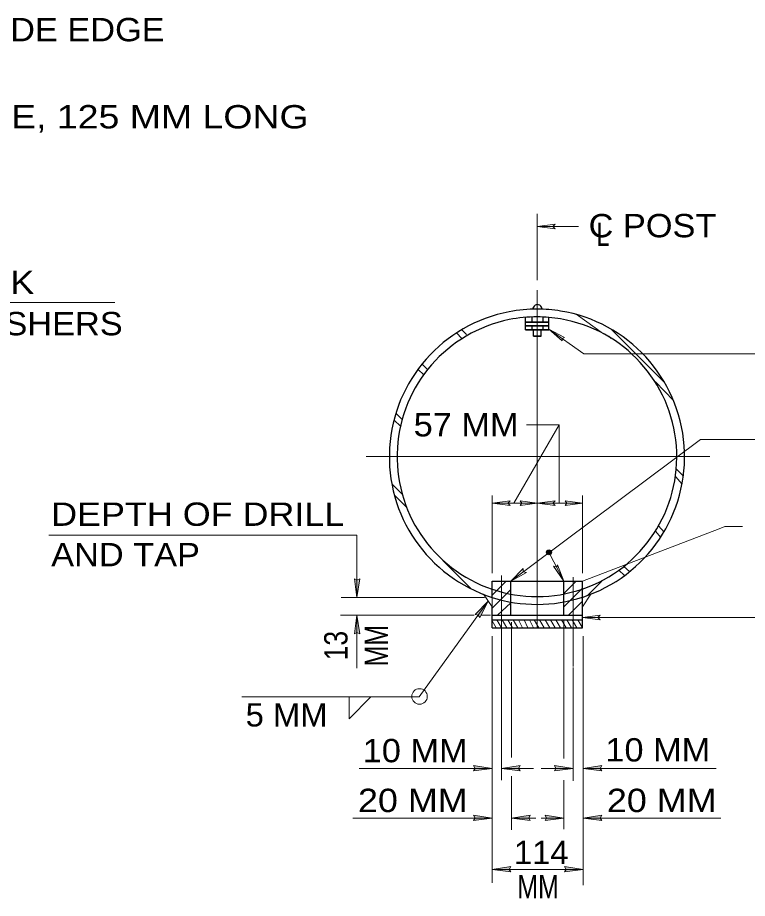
# Model space of a CAD drawing. Extents: x 312601.858 to 312602.699, y 144420.109 to 144420.704.
# Drawn here: x 312602.3399 to 312602.4337, y 144420.327 to 144420.4402 of the extents above; entities that cross this region are included whole.
import ezdxf
from ezdxf.enums import TextEntityAlignment as Align

# ---------------------------------------------------------------- set-up
doc = ezdxf.new("R2010")
doc.units = 0
doc.header["$LTSCALE"] = 0.0012
for name, pattern in [('DOT_DASHED', [7.7, 5, -1.2, 0.3, -1.2]), ('LONG_DASH_SHORT_DASH', [9.9, 6, -1.2, 1.5, -1.2]), ('LONG_DASHED', [7.5, 6, -1.5])]:
    doc.linetypes.add(name, pattern=pattern)
for name, color, linetype, lineweight in [('1', 7, 'Continuous', 25), ('2', 7, 'Continuous', 25), ('39', 7, 'Continuous', 13)]:
    doc.layers.add(name, color=color, linetype=linetype, lineweight=lineweight)

msp = doc.modelspace()

# ---------------------------------------------------------------- hatches: boundary and pattern name
at = {"layer": '1'}
msp.add_hatch(color=256, dxfattribs=at).paths.add_polyline_path([(312602.408516, 144420.3715, 1), (312602.407884, 144420.3715, 1)])
at = {"layer": '39'}
for points in [[(312602.3835, 144420.3679), (312602.3839, 144420.3681), (312602.3835, 144420.3657), (312602.3832, 144420.3681)], [(312602.3991, 144420.3634), (312602.3987, 144420.3635), (312602.4004, 144420.3652), (312602.3993, 144420.3631)], [(312602.3835, 144420.3612), (312602.3832, 144420.361), (312602.3835, 144420.3634), (312602.3839, 144420.361)], [(312602.3987, 144420.3437), (312602.3985, 144420.3441), (312602.4009, 144420.3437), (312602.3985, 144420.3434)], [(312602.4043, 144420.3437), (312602.4045, 144420.3434), (312602.4021, 144420.3437), (312602.4045, 144420.3441)], [(312602.4091, 144420.3437), (312602.4089, 144420.3441), (312602.4113, 144420.3437), (312602.4089, 144420.3434)], [(312602.4148, 144420.3437), (312602.415, 144420.3434), (312602.4126, 144420.3437), (312602.415, 144420.3441)], [(312602.3987, 144420.3373), (312602.3985, 144420.3377), (312602.4009, 144420.3373), (312602.3985, 144420.337)], [(312602.4056, 144420.3373), (312602.4058, 144420.337), (312602.4034, 144420.3373), (312602.4058, 144420.3377)], [(312602.4079, 144420.3373), (312602.4077, 144420.3377), (312602.4101, 144420.3373), (312602.4077, 144420.337)], [(312602.4148, 144420.3373), (312602.415, 144420.337), (312602.4126, 144420.3373), (312602.415, 144420.3377)], [(312602.4031, 144420.3307), (312602.4033, 144420.3304), (312602.4009, 144420.3307), (312602.4033, 144420.3311)], [(312602.4104, 144420.3307), (312602.4102, 144420.3311), (312602.4126, 144420.3307), (312602.4102, 144420.3304)]]:
    msp.add_hatch(color=256, dxfattribs=at).paths.add_polyline_path(points)

# ---------------------------------------------------------------- linework, layer by layer
at = {"layer": '1', "lineweight": 13}
for p, q in [((312602.4067, 144420.4065), (312602.4067, 144420.415)), ((312602.4067, 144420.4134), (312602.412, 144420.4134)), ((312602.2746, 144420.4036), (312602.3524, 144420.4036)), ((312602.4117, 144420.4021), (312602.4152, 144420.3996)), ((312602.3976, 144420.3995), (312602.397, 144420.4001)), ((312602.4082, 144420.4002), (312602.4127, 144420.397)), ((312602.4231, 144420.3933), (312602.4162, 144420.4002)), ((312602.397, 144420.399), (312602.3963, 144420.3997)), ((312602.4162, 144420.399), (312602.4159, 144420.3993)), ((312602.4127, 144420.397), (312602.4675, 144420.397)), ((312602.3926, 144420.395), (312602.3919, 144420.3957)), ((312602.3921, 144420.3943), (312602.3914, 144420.395)), ((312602.4242, 144420.391), (312602.4219, 144420.3934)), ((312602.3893, 144420.3886), (312602.3885, 144420.3894)), ((312602.3891, 144420.3877), (312602.3883, 144420.3885)), ((312602.4033, 144420.3678), (312602.4277, 144420.386)), ((312602.4277, 144420.386), (312602.4347, 144420.386)), ((312602.4255, 144420.3813), (312602.4246, 144420.3822)), ((312602.4253, 144420.3803), (312602.4245, 144420.3812)), ((312602.3893, 144420.379), (312602.388, 144420.3803)), ((312602.3899, 144420.3773), (312602.3883, 144420.3789)), ((312602.4009, 144420.3788), (312602.4009, 144420.3688)), ((312602.4125, 144420.3788), (312602.4125, 144420.3688)), ((312602.4125, 144420.3678), (312602.4301, 144420.3745)), ((312602.4226, 144420.3734), (312602.4219, 144420.3742)), ((312602.423, 144420.3741), (312602.4223, 144420.3749)), ((312602.4301, 144420.3745), (312602.4308, 144420.3748)), ((312602.4308, 144420.3748), (312602.4331, 144420.3748)), ((312602.3835, 144420.3737), (312602.3439, 144420.3737)), ((312602.4101, 144420.3678), (312602.4082, 144420.3715)), ((312602.3982, 144420.3668), (312602.3946, 144420.3704)), ((312602.4186, 144420.369), (312602.4178, 144420.3697)), ((312602.4179, 144420.3685), (312602.4172, 144420.3692)), ((312602.396, 144420.3681), (312602.3961, 144420.368)), ((312602.4009, 144420.3677), (312602.4009, 144420.3678)), ((312602.4009, 144420.366), (312602.4027, 144420.3678)), ((312602.4101, 144420.3662), (312602.4117, 144420.3678)), ((312602.4132, 144420.366), (312602.415, 144420.3678)), ((312602.4009, 144420.3643), (312602.4033, 144420.3667)), ((312602.4101, 144420.3645), (312602.4125, 144420.3669)), ((312602.3815, 144420.3657), (312602.3999, 144420.3657)), ((312602.4016, 144420.3634), (312602.4033, 144420.365)), ((312602.4107, 144420.3634), (312602.4125, 144420.3652)), ((312602.3814, 144420.3634), (312602.3986, 144420.3634)), ((312602.3995, 144420.3634), (312602.4007, 144420.3634)), ((312602.4014, 144420.3618), (312602.4009, 144420.3627)), ((312602.4021, 144420.3618), (312602.4015, 144420.3628)), ((312602.4028, 144420.3618), (312602.4022, 144420.3628)), ((312602.4035, 144420.3618), (312602.4029, 144420.3628)), ((312602.4034, 144420.3451), (312602.4034, 144420.3625)), ((312602.4042, 144420.3618), (312602.4036, 144420.3628)), ((312602.4048, 144420.3618), (312602.4043, 144420.3628)), ((312602.4055, 144420.3618), (312602.405, 144420.3628)), ((312602.4062, 144420.3618), (312602.4057, 144420.3628)), ((312602.4069, 144420.3618), (312602.4063, 144420.3628)), ((312602.4076, 144420.3618), (312602.407, 144420.3628)), ((312602.4083, 144420.3618), (312602.4077, 144420.3628)), ((312602.409, 144420.3618), (312602.4084, 144420.3628)), ((312602.4097, 144420.3618), (312602.4091, 144420.3628)), ((312602.4104, 144420.3618), (312602.4098, 144420.3628)), ((312602.4101, 144420.345), (312602.4101, 144420.3628)), ((312602.4111, 144420.3618), (312602.4105, 144420.3628)), ((312602.4118, 144420.3618), (312602.4112, 144420.3628)), ((312602.4125, 144420.3618), (312602.4119, 144420.3628)), ((312602.4124, 144420.3634), (312602.4125, 144420.3635)), ((312602.4125, 144420.3631), (312602.4301, 144420.3631)), ((312602.4301, 144420.3631), (312602.4308, 144420.3631)), ((312602.4308, 144420.3631), (312602.4938, 144420.3631)), ((312602.4009, 144420.329), (312602.4009, 144420.3607)), ((312602.4126, 144420.3287), (312602.4126, 144420.3607)), ((312602.4021, 144420.3437), (312602.4021, 144420.357)), ((312602.4113, 144420.3421), (312602.4113, 144420.3567)), ((312602.3838, 144420.3437), (312602.4009, 144420.3437)), ((312602.4072, 144420.3437), (312602.4113, 144420.3437)), ((312602.4126, 144420.3437), (312602.4297, 144420.3437)), ((312602.4034, 144420.3358), (312602.4034, 144420.3427)), ((312602.4101, 144420.3359), (312602.4101, 144420.3422)), ((312602.383, 144420.3373), (312602.4009, 144420.3373)), ((312602.4034, 144420.3373), (312602.4065, 144420.3373)), ((312602.4072, 144420.3373), (312602.4101, 144420.3373)), ((312602.4126, 144420.3373), (312602.4303, 144420.3373)), ((312602.4009, 144420.3307), (312602.4126, 144420.3307))]:
    msp.add_line(p, q, dxfattribs=at)
at = {"layer": '1', "linetype": 'LONG_DASH_SHORT_DASH', "lineweight": 13}
for p, q in [((312602.4067, 144420.4072), (312602.4067, 144420.4077)), ((312602.3859, 144420.3838), (312602.3847, 144420.3838))]:
    msp.add_line(p, q, dxfattribs=at)
at = {"layer": '1', "linetype": 'DOT_DASHED', "lineweight": 13}
for p, q in [((312602.4067, 144420.3618), (312602.4067, 144420.4052)), ((312602.3847, 144420.3838), (312602.4289, 144420.3838))]:
    msp.add_line(p, q, dxfattribs=at)
at = {"layer": '1'}
for p, q in [((312602.4052, 144420.4001), (312602.4052, 144420.4017)), ((312602.4052, 144420.4011), (312602.4082, 144420.4011)), ((312602.4082, 144420.4011), (312602.4052, 144420.4011)), ((312602.406, 144420.4017), (312602.406, 144420.4011)), ((312602.4074, 144420.4017), (312602.4074, 144420.4011)), ((312602.4082, 144420.4001), (312602.4082, 144420.4017)), ((312602.4052, 144420.4006), (312602.4082, 144420.4006)), ((312602.4082, 144420.4006), (312602.4052, 144420.4006)), ((312602.4052, 144420.4001), (312602.4082, 144420.4001)), ((312602.4082, 144420.4001), (312602.4052, 144420.4001)), ((312602.406, 144420.4006), (312602.406, 144420.4001)), ((312602.4062, 144420.3993), (312602.4062, 144420.4001)), ((312602.4074, 144420.4006), (312602.4074, 144420.4001)), ((312602.4072, 144420.3993), (312602.4062, 144420.3993)), ((312602.4009, 144420.3678), (312602.4125, 144420.3678)), ((312602.4009, 144420.3657), (312602.4009, 144420.3678)), ((312602.4033, 144420.3634), (312602.4033, 144420.3678)), ((312602.4101, 144420.3634), (312602.4101, 144420.3678)), ((312602.4125, 144420.3618), (312602.4125, 144420.3678)), ((312602.4009, 144420.3618), (312602.4009, 144420.3645)), ((312602.4009, 144420.3634), (312602.4125, 144420.3634)), ((312602.4009, 144420.3628), (312602.4125, 144420.3628)), ((312602.4009, 144420.3618), (312602.4125, 144420.3618))]:
    msp.add_line(p, q, dxfattribs=at)
at = {"layer": '1', "lineweight": 13}
for points in [[(312602.409, 144420.4131), (312602.4067, 144420.4134), (312602.409, 144420.4137), (312602.4087, 144420.4134)], [(312602.4099, 144420.3987), (312602.4082, 144420.4002), (312602.4102, 144420.3991), (312602.4099, 144420.399)], [(312602.4032, 144420.3775), (312602.4009, 144420.3778), (312602.4032, 144420.3781), (312602.4029, 144420.3778)], [(312602.4045, 144420.3781), (312602.4067, 144420.3778), (312602.4045, 144420.3775), (312602.4047, 144420.3778)], [(312602.409, 144420.3775), (312602.4067, 144420.3778), (312602.409, 144420.3781), (312602.4087, 144420.3778)], [(312602.4103, 144420.3781), (312602.4125, 144420.3778), (312602.4103, 144420.3775), (312602.4105, 144420.3778)], [(312602.4053, 144420.3689), (312602.4033, 144420.3678), (312602.4049, 144420.3694), (312602.4049, 144420.369)], [(312602.4093, 144420.3699), (312602.4101, 144420.3678), (312602.4088, 144420.3697), (312602.4092, 144420.3696)], [(312602.4148, 144420.3628), (312602.4125, 144420.3631), (312602.4148, 144420.3634), (312602.4145, 144420.3631)]]:
    msp.add_lwpolyline(points, close=True, dxfattribs=at)
at = {"layer": '1'}
msp.add_lwpolyline([(312602.4062, 144420.3993), (312602.4072, 144420.3993), (312602.4072, 144420.4001)], dxfattribs=at)
at = {"layer": '1', "lineweight": 13}
for points in [[(312602.4009, 144420.3778), (312602.4067, 144420.3778), (312602.4125, 144420.3778)], [(312602.4009, 144420.3657), (312602.4009, 144420.3645), (312602.3998, 144420.3661)], [(312602.4125, 144420.3657), (312602.4125, 144420.3645), (312602.4136, 144420.3661)], [(312602.4004, 144420.3652), (312602.3915, 144420.3529), (312602.3687, 144420.3529)], [(312602.3825, 144420.3529), (312602.3825, 144420.3501), (312602.3853, 144420.3529)], [(312602.4021, 144420.3422), (312602.4021, 144420.3437), (312602.4062, 144420.3437)]]:
    msp.add_lwpolyline(points, dxfattribs=at)
at = {"layer": '1', "linetype": 'LONG_DASH_SHORT_DASH', "lineweight": 13}
for points in [[(312602.4021, 144420.3568), (312602.4021, 144420.3571), (312602.4021, 144420.3685)], [(312602.4113, 144420.3568), (312602.4113, 144420.3571), (312602.4113, 144420.3683)]]:
    msp.add_lwpolyline(points, dxfattribs=at)
at = {"layer": '1'}
msp.add_circle((312602.4082, 144420.3715), 0.000316, dxfattribs=at)
at = {"layer": '1', "lineweight": 13}
msp.add_circle((312602.391558, 144420.352965), 0.000999, dxfattribs=at)
at = {"layer": '1'}
for centre, radius, start, end in [((312602.406717, 144420.40274), 0.000599, 359.05298, 180.94702), ((312602.406717, 144420.40274), 0.000599, 359.05298, 180.94702), ((312602.406658, 144420.383783), 0.018982, 100.80256, 252.34271), ((312602.406658, 144420.383783), 0.018982, 89.8725, 100.80256), ((312602.406658, 144420.383783), 0.018982, 80.77758, 89.8725), ((312602.406658, 144420.383783), 0.018982, 287.774, 80.77758), ((312602.406658, 144420.383783), 0.017983, 101.41055, 251.32655), ((312602.406658, 144420.383783), 0.017983, 89.86542, 101.41055), ((312602.406658, 144420.383783), 0.017983, 80.26037, 89.86542), ((312602.406658, 144420.383783), 0.017983, 288.79737, 80.26037)]:
    msp.add_arc(centre, radius, start, end, dxfattribs=at)
at = {"layer": '1', "lineweight": 13}
for centre, start, end in [((312602.406658, 144420.383783), 248.87866, 252.34271), ((312602.406742, 144420.383783), 287.65729, 291.12134)]:
    msp.add_arc(centre, 0.018982, start, end, dxfattribs=at)
at = {"layer": '1', "linetype": 'LONG_DASHED'}
for radius, start, end in [(0.017983, 251.32655, 288.95781), (0.018982, 252.34271, 287.92509)]:
    msp.add_arc((312602.406658, 144420.383783), radius, start, end, dxfattribs=at)
at = {"layer": '2', "lineweight": 13}
for p, q in [((312602.4095, 144420.3879), (312602.4037, 144420.3778)), ((312602.3835, 144420.3737), (312602.3835, 144420.3657)), ((312602.3835, 144420.3634), (312602.3835, 144420.3566))]:
    msp.add_line(p, q, dxfattribs=at)
msp.add_lwpolyline([(312602.4053, 144420.3879), (312602.4095, 144420.3879), (312602.4095, 144420.3778)], dxfattribs=at)
at = {"layer": '39'}
for points in [[(312602.3835, 144420.3679), (312602.3839, 144420.3681), (312602.3835, 144420.3657), (312602.3832, 144420.3681)], [(312602.3991, 144420.3634), (312602.3987, 144420.3635), (312602.4004, 144420.3652), (312602.3993, 144420.3631)], [(312602.3835, 144420.3612), (312602.3832, 144420.361), (312602.3835, 144420.3634), (312602.3839, 144420.361)], [(312602.3987, 144420.3437), (312602.3985, 144420.3441), (312602.4009, 144420.3437), (312602.3985, 144420.3434)], [(312602.4043, 144420.3437), (312602.4045, 144420.3434), (312602.4021, 144420.3437), (312602.4045, 144420.3441)], [(312602.4091, 144420.3437), (312602.4089, 144420.3441), (312602.4113, 144420.3437), (312602.4089, 144420.3434)], [(312602.4148, 144420.3437), (312602.415, 144420.3434), (312602.4126, 144420.3437), (312602.415, 144420.3441)], [(312602.3987, 144420.3373), (312602.3985, 144420.3377), (312602.4009, 144420.3373), (312602.3985, 144420.337)], [(312602.4056, 144420.3373), (312602.4058, 144420.337), (312602.4034, 144420.3373), (312602.4058, 144420.3377)], [(312602.4079, 144420.3373), (312602.4077, 144420.3377), (312602.4101, 144420.3373), (312602.4077, 144420.337)], [(312602.4148, 144420.3373), (312602.415, 144420.337), (312602.4126, 144420.3373), (312602.415, 144420.3377)], [(312602.4031, 144420.3307), (312602.4033, 144420.3304), (312602.4009, 144420.3307), (312602.4033, 144420.3311)], [(312602.4104, 144420.3307), (312602.4102, 144420.3311), (312602.4126, 144420.3307), (312602.4102, 144420.3304)]]:
    msp.add_lwpolyline(points, close=True, dxfattribs=at)

# ---------------------------------------------------------------- texts
at = {"layer": '1'}
for s, width, p in [('ROUND AND SMOOTH INSIDE EDGE', 1.1, (312602.2818, 144420.4372)), ('41 MM o CONDUIT NIPPLE, 125 MM LONG', 1.2, (312602.2818, 144420.426)), ('M12 U-BOLT WITH HI-LOCK', 1.15, (312602.2818, 144420.4047)), ('NUTS AND STANDARD WASHERS', 1.1, (312602.2818, 144420.3994)), ('DEPTH OF DRILL', 1.15, (312602.3442, 144420.3749)), ('AND TAP', 1.1, (312602.3442, 144420.3697)), ('5 MM', 1.05, (312602.3692, 144420.3491))]:
    msp.add_text(s, height=0.003, dxfattribs=dict(at, width=width)).set_placement(p)
at = {"layer": '1', "width": 0.75}
msp.add_text('L', height=0.003, dxfattribs=at).set_placement((312602.41515, 144420.4109), align=Align.CENTER)
at = {"layer": '2'}
for s, width, p in [('C POST', 1.1, (312602.4133, 144420.412)), ('114 ', 1.05, (312602.4037, 144420.3314))]:
    msp.add_text(s, height=0.003, dxfattribs=dict(at, width=width)).set_placement(p)
for s, width, p in [('57 MM', 1.1, (312602.39755, 144420.3864)), ('10 MM', 1.1, (312602.391, 144420.3445)), ('10 MM', 1.1, (312602.4222, 144420.3446)), ('20 MM', 1.15, (312602.3907, 144420.3381)), ('20 MM', 1.15, (312602.4227, 144420.3381)), ('MM', 0.8, (312602.4068, 144420.327))]:
    msp.add_text(s, height=0.003, dxfattribs=dict(at, width=width)).set_placement(p, align=Align.CENTER)
for s, width, p in [('MM', 0.8, (312602.3875, 144420.3595)), ('13', 0.85, (312602.3823, 144420.3595))]:
    msp.add_text(s, height=0.003, rotation=90, dxfattribs=dict(at, width=width)).set_placement(p, align=Align.CENTER)

doc.saveas('drawing.dxf')
